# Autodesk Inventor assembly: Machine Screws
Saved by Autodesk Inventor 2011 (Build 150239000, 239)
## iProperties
Created: 2008-03
Part Number: Machine Screws
Document SubType Name: Assembly
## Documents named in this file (2)
- C:\Data Folder\VEX 2011\Inventor Datasets\Unit 15\Components\Machine Screws.iam
- C:\Data Folder\VEX 2011\Inventor Datasets\Unit 15\Components\ANSI B18.6.3 - 1-64 UNC - 0.125(9).ipt
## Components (8 placed, 1 different names)
1. Cross Recessed Fillister Head Machine Screw - Type IA - Inch 1 - 64 - 1/8:1
2. Cross Recessed Fillister Head Machine Screw - Type IA - Inch 1 - 64 - 1/8:2
3. Cross Recessed Fillister Head Machine Screw - Type IA - Inch 1 - 64 - 1/8:3
4. Cross Recessed Fillister Head Machine Screw - Type IA - Inch 1 - 64 - 1/8:4
5. Cross Recessed Fillister Head Machine Screw - Type IA - Inch 1 - 64 - 1/8:5
6. Cross Recessed Fillister Head Machine Screw - Type IA - Inch 1 - 64 - 1/8:6
7. Cross Recessed Fillister Head Machine Screw - Type IA - Inch 1 - 64 - 1/8:7
8. Cross Recessed Fillister Head Machine Screw - Type IA - Inch 1 - 64 - 1/8:8
